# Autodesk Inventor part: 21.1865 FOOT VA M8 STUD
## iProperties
Created: 2007-11
Part Number: 21.1865 FOOT VA M8 STUD
Material: Stainless Steel
Document SubType Name: Modeling
Designer: Andy Moles
Density: 8.08 g/cm^3
Mass: 40.5265 g
Surface Area: 21.7922 cm^2
Volume: 5.01566 cm^3
Author: Andy Moles
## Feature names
1. Base1
